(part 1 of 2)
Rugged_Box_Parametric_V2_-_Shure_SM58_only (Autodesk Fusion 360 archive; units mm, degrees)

design "Rugged Box Parametric V2 - Shure SM58 only" references "Shure SM58"
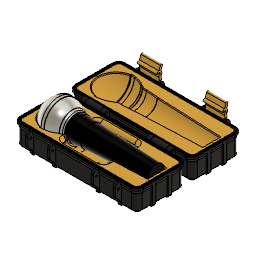
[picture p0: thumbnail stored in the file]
parameter "InnerBoxDepth" = 64 comment "Inner depth"
parameter "InnerBoxWidth" = 170 comment "Inner width"
parameter "InnerBoxBottomHeight" = 30 comment "Inner height of the bottom part"
parameter "ScrewDiameter" = 3 comment "M3 => 3 mm"
parameter "InnerCornerRadius" = 3 comment "Corner radius on the bottom (bottom of champfer)"
parameter "HingeLatchOffset" = 20 comment "Offset of the hinge and latch from inner wall"
parameter "WallThickness" = 2.4 comment "Thickness of the walls"
parameter "RibWidth" = 5 comment "Width of the ribs on the sides"
parameter "InnerChamferSize" = 2 comment "Size of the chamfer on the top and bottom inside the box"
parameter "ScrewThreadDiameter" = 2.85 (= "ScrewDiameter - 0.15 mm") comment "Diameter of the inner holes where you screw in the screw"
parameter "ScrewLength" = 35 comment "Length of the screw to use"
parameter "HingeWidthTolerance" = 0.25 comment "Tolerance of the hinge (width)"
parameter "RibOffset" = 18 comment "Offset of the ribs from inner wall"
parameter "LatchDistance" = 16 comment "Distance between the two screws of the latch"
parameter "InnerBoxLidHeight" = 30 comment "Inner height of the lid"
parameter "HingeLatchHolesTolerance" = 0.4 comment "Tolerance of the hinge and latch holes"
parameter "LatchWidthTolerance" = 0.4 comment "Tollerance of the latch width"
parameter "SealHeight" = 1.4 comment "Height of the seal"
parameter "HingeLatchRibWidth" = 3.2 comment "Width of the ribs for the hinges and latches"
parameter "BoxLatchRibChamferOffset" = 17
parameter "HingeRibChamferOffset" = 5 comment "Offset of the big chamfer on the rib of the hinge side"
parameter "HingeOuterDiameter" = 6.8
parameter "LidLatchRibChamferOffset" = 10 comment "Offset of the big chamfer on the rib of the lid"
parameter "HingeOuterExtend" = 3
sketch "Sketch1" plane through (0, 0, 0) normal (0, 1, 0) x axis (1, 0, 0)
  line L1 (-27, -83) -> (27, -83)
  line L2 (-30, 80) -> (-30, -80)
  line L3 (27, 83) -> (-27, 83)
  line L4 (30, -80) -> (30, 80)
  line L5 (-30, 83) -> (30, -83)
  line L6 (30, 83) -> (-30, -83)
  arc A1 centre (-27, 80) radius 3 clockwise from (-30, 80) to (-27, 83)
  arc A2 centre (27, 80) radius 3 clockwise from (27, 83) to (30, 80)
  arc A3 centre (27, -80) radius 3 clockwise from (30, -80) to (27, -83)
  arc A4 centre (-27, -80) radius 3 clockwise from (-27, -83) to (-30, -80)
  point P6 (0, 0)
  point P1 (0, 0)
  point P4 (-30, 83)
  point P5 (30, 83)
  point P2 (30, -83)
  point P3 (-30, -83)
  horizontal L1
  perpendicular L1 L2
  parallel L1 L3
  parallel L2 L4
  coincident L5 P6
  coincident L6 P6
  coincident P1 P6
  coincident P4 L3
  coincident P4 L2
  tangent L3 A1
  tangent L2 A1
  coincident P5 L3
  coincident P5 L4
  tangent L3 A2
  tangent L4 A2
  coincident P2 L4
  coincident P2 L1
  tangent L4 A3
  tangent L1 A3
  coincident P3 L1
  coincident P3 L2
  tangent L1 A4
  tangent L2 A4
  equal A1 A2
  equal A1 A4
  equal A3 A4
  dimension "d6" distance L1 L3 = 166 (= "InnerBoxWidth - 2 * InnerChamferSize")
  dimension "d7" distance L2 L4 = 60 (= "InnerBoxDepth - 2 * InnerChamferSize")
  dimension "d9" radius A2 = 3 (= "InnerCornerRadius")
sketch "Sketch2" plane through (0, 0, 0) normal (0, 0, 1) x axis (1, 0, 0)
  line L1 (30, 0) -> (0, 0)
  line L2 (30, 2.4) -> (30, 0)
  line L3 (32, 32.4) -> (32, 4.4)
  line L4 (33.23, 32.4) -> (32, 32.4)
  line L5 (33.23, 30.4) -> (33.23, 32.4)
  line L6 (35.03, 30.4) -> (33.23, 30.4)
  line L7 (35.03, 32.4) -> (35.03, 30.4)
  line L8 (36.26, 32.4) -> (35.03, 32.4)
  line L9 (36.26, 29.4) -> (36.26, 32.4)
  line L10 (30, 0) -> (40.1865, 0)
  line L11 (34.4, 29.4) -> (36.26, 29.4)
  line L12 (34.4, 25) -> (34.4, 29.4)
  line L13 (34.4, 3.4059) -> (34.4, 25)
  line L14 (36.26, 29.4) -> (34.4, 25)
  line L15 (30, 2.4) -> (32, 4.4)
  line L16 (34.4, 3.4059) -> (30.9941, 0)
  line L17 (43.26, 3.0735) -> (40.1865, 0)
  line L18 (38.26, 32.4) -> (36.26, 32.4)
  line L19 (43.26, 3.0735) -> (43.26, 27.4)
  line L20 (0, 60) -> (0, 0)
  line L21 (-43.26, 3.0735) -> (-43.26, 27.4)
  line L22 (-33.23, 30.4) -> (-33.23, 32.4)
  line L23 (-36.26, 29.4) -> (-34.4, 25)
  line L24 (-32, 32.4) -> (-32, 4.4)
  line L25 (-30, 2.4) -> (-30, 0)
  line L26 (-35.03, 30.4) -> (-33.23, 30.4)
  line L27 (-34.4, 3.4059) -> (-30.9941, 0)
  line L28 (-34.4, 3.4059) -> (-34.4, 25)
  line L29 (-30, 2.4) -> (-32, 4.4)
  line L30 (-36.26, 29.4) -> (-36.26, 32.4)
  line L31 (-43.26, 3.0735) -> (-40.1865, 0)
  line L32 (-34.4, 25) -> (-34.4, 29.4)
  line L33 (-36.26, 32.4) -> (-35.03, 32.4)
  line L34 (-35.03, 32.4) -> (-35.03, 30.4)
  line L35 (-30, 0) -> (-40.1865, 0)
  line L36 (-34.4, 29.4) -> (-36.26, 29.4)
  line L37 (-33.23, 32.4) -> (-32, 32.4)
  line L38 (32, 29.4) -> (34.4, 29.4)
  line L39 (-32, 29.4) -> (-34.4, 29.4)
  line L40 (-43.26, 27.4) -> (-43.26, 32.4)
  line L41 (-36.46, 32.4) -> (-36.26, 32.4)
  line L42 (-32, 19.7317) -> (-42.2642, 29.9958)
  line L43 (-39.091, 29.9958) -> (-42.2642, 29.9958)
  line L44 (-36.26, 32.4) -> (-39.86, 32.4)
  line L45 (36.26, 2.6355) -> (33.6245, 0)
  line L46 (36.26, 8.4) -> (36.26, 2.6355)
  line L47 (43.26, 15.4) -> (36.26, 8.4)
  line L48 (-36.26, 2.6355) -> (-33.6245, 0)
  line L49 (-36.26, 20.4) -> (-36.26, 2.6355)
  line L50 (-43.26, 27.4) -> (-36.26, 20.4)
  arc A1 centre (38.26, 27.4) radius 5 clockwise from (38.26, 32.4) to (43.26, 27.4)
  circle C1 centre (38.76, 24.4) radius 1.7
  circle C2 centre (-39.86, 32.4) radius 1.7
  circle C3 centre (-39.86, 32.4) radius 3.4
  point P1 (0, 0)
  point P2 (0, 0)
  point P15 (30.9941, 0)
  point P18 (43.26, 32.4)
  point P24 (0, 0)
  point P3 (30, 0)
  point P40 (-30, 0)
  point P4 (30, 2.4)
  point P42 (-30, 2.4)
  point P5 (32, 32.4)
  point P38 (-32, 32.4)
  point P6 (33.23, 32.4)
  point P41 (-33.23, 32.4)
  point P7 (33.23, 30.4)
  point P43 (-33.23, 30.4)
  point P8 (35.03, 30.4)
  point P39 (-35.03, 30.4)
  point P9 (35.03, 32.4)
  point P34 (-35.03, 32.4)
  point P10 (36.26, 32.4)
  point P30 (-36.26, 32.4)
  point P11 (36.26, 29.4)
  point P33 (-36.26, 29.4)
  point P12 (34.4, 29.4)
  point P36 (-34.4, 29.4)
  point P13 (34.4, 25)
  point P29 (-34.4, 25)
  point P14 (32, 4.4)
  point P35 (-32, 4.4)
  point P32 (-30.9941, 0)
  point P16 (34.4, 3.4059)
  point P27 (-34.4, 3.4059)
  point P17 (40.1865, 0)
  point P26 (-40.1865, 0)
  point P37 (-43.26, 32.4)
  point P19 (43.26, 3.0735)
  point P31 (-43.26, 3.0735)
  point P21 (43.26, 27.4)
  point P28 (-43.26, 27.4)
  point P44 (32, 29.4)
  point P45 (-32, 29.4)
  point P48 (-43.26, 32.4)
  point P49 (-36.46, 32.4)
  point P50 (-42.2642, 29.9958)
  point P52 (-32, 19.7317)
  point P46 (-39.86, 32.4)
  point P53 (-39.86, 32.4)
  point P54 (33.6245, 0)
  point P57 (43.26, 15.4)
  point P58 (-33.6245, 0)
  point P55 (36.26, 2.6355)
  point P59 (-36.26, 2.6355)
  point P61 (-43.26, 27.4)
  point P23 (38.76, 24.4)
  coincident P1 P2
  horizontal L1
  perpendicular L1 L2
  perpendicular L3 L4
  perpendicular L4 L5
  perpendicular L5 L6
  perpendicular L6 L7
  perpendicular L7 L8
  perpendicular L8 L9
  perpendicular L2 L10
  perpendicular L9 L11
  perpendicular L11 L12
  perpendicular L10 L13
  coincident L10 P15
  vertical L3
  perpendicular L9 L18
  perpendicular L8 L19
  coincident P18 L18
  coincident P18 L19
  tangent L18 A1
  tangent L19 A1
  coincident P1 P24
  perpendicular L1 L20
  symmetric P3 L20 P40
  symmetric P4 L20 P42
  symmetric P5 L20 P38
  symmetric P6 L20 P41
  symmetric P7 L20 P43
  symmetric P8 L20 P39
  symmetric P9 L20 P34
  symmetric P10 L20 P30
  symmetric P11 L20 P33
  symmetric P12 L20 P36
  symmetric P13 L20 P29
  symmetric P14 L20 P35
  symmetric P15 L20 P32
  symmetric P16 L20 P27
  symmetric P17 L20 P26
  symmetric P18 L20 P37
  symmetric P19 L20 P31
  symmetric P21 L20 P28
  coincident L3 P44
  perpendicular L3 L38
  coincident L24 P45
  perpendicular L24 L39
  concentric C2 C3
  coincident P37 P48
  coincident C3 P49
  horizontal L43
  coincident C3 P50
  tangent C3 L42
  coincident L24 P52
  coincident P46 P53
  perpendicular L30 L44
  horizontal L41
  coincident L10 P54
  perpendicular L10 L46
  coincident L19 P57
  collinear L9 L46
  parallel L16 L45
  symmetric L20 P54 P58
  symmetric L20 P55 P59
  parallel L45 L47
  parallel L28 L49
  coincident L21 P61
  parallel L48 L50
  dimension "d12" distance P2 P3 = 30 (= "InnerBoxDepth / 2 - InnerChamferSize")
  dimension "d13" distance P3 P4 = 2.4 (= "WallThickness")
  dimension "d15" distance P5 P6 = 1.23
  dimension "d16" distance P6 P7 = 2
  dimension "d17" distance P7 P8 = 1.8
  dimension "d18" distance P8 P9 = 2
  dimension "d20" distance P10 P11 = 3
  dimension "d23" distance P12 P13 = 4.4
  dimension "d26" distance L15 L16 = 2.4 (= "WallThickness")
  dimension "d27" distance P4 P14 = 2 (= "InnerChamferSize")
  dimension "d28" distance P4 P14 = 2 (= "InnerChamferSize")
  dimension "d29" distance P3 L8 = 32.4 (= "InnerBoxBottomHeight + WallThickness")
  dimension "d30" distance L16 L17 = 6.5
  dimension "d61" distance P10 P18 = 7
  dimension "d62" radius A1 = 5
  dimension "d63" diameter C1 = 3.4 (= "ScrewDiameter + HingeLatchHolesTolerance")
  dimension "d64" distance L18 P23 = 8 (= "LatchDistance / 2")
  dimension "d65" distance L19 P23 = 4.5
  dimension "d129" distance L7 L9 = 1.23
  dimension "d131" distance L3 L13 = 2.4 (= "WallThickness")
  dimension "d137" diameter C2 = 3.4 (= "ScrewDiameter + HingeLatchHolesTolerance")
  dimension "d138" distance P30 P46 = 3.6 (= "HingeOuterDiameter / 2 + 0.2 mm")
  dimension "d139" diameter C3 = 6.8 (= "HingeOuterDiameter")
  dimension "d140" angle L42 L43 = 45
  dimension "d111" distance L16 L45 = 1.86 (= "d113")
  dimension "d113" distance L9 L12 = 1.86
  dimension "d114" distance L18 P57 = 17 (= "BoxLatchRibChamferOffset")
  dimension "d123" distance L44 P61 = 5 (= "HingeRibChamferOffset")
extrude "Extrude1" new body sketch "Sketch1" profile of L1 L2 L3 L4 A1 A2 A3 A4 along normal blind 2.4 (= "WallThickness")
sweep "Sweep1" sketch "Sketch2" TwistAngle 0 TaperAngle 0
work_plane "WorkPlane2" AlongDistance -14 (= "RibOffset - InnerBoxDepth / 2")
sketch "Sketch4" plane through (-14, 0, 0) normal (1, 0, 0) x axis (0, 0, -1)
  line L1 (-83, 0) -> (0, 0)
  line L2 (-83, 2.4) -> (-83, 0)
  line L3 (-85, 2.4) -> (-83, 2.4)
  line L4 (-85, 4.4) -> (-85, 2.4)
  line L5 (-83, 2.4) -> (-85, 4.4)
  line L6 (-85, 5) -> (-85, 2.4)
  line L7 (-85, 29.4) -> (-85, 2.4)
  line L8 (-89.26, 29.4) -> (-85, 29.4)
  line L9 (-89.26, 2.6355) -> (-89.26, 29.4)
  line L10 (-83, 0) -> (-86.6245, 0)
  line L11 (-89.26, 2.6355) -> (-86.6245, 0)
  line L12 (0, 70) -> (0, 0)
  line L13 (89.26, 2.6355) -> (86.6245, 0)
  line L14 (83, 0) -> (86.6245, 0)
  line L15 (85, 5) -> (85, 2.4)
  line L16 (85, 29.4) -> (85, 2.4)
  line L17 (83, 2.4) -> (85, 4.4)
  line L18 (85, 4.4) -> (85, 2.4)
  line L19 (89.26, 29.4) -> (85, 29.4)
  line L20 (89.26, 2.6355) -> (89.26, 29.4)
  line L21 (83, 2.4) -> (83, 0)
  line L22 (85, 2.4) -> (83, 2.4)
  point P1 (0, 0)
  point P2 (0, 0)
  point P7 (-85, 5)
  point P12 (0, 0)
  point P3 (-83, 0)
  point P16 (83, 0)
  point P4 (-83, 2.4)
  point P18 (83, 2.4)
  point P5 (-85, 2.4)
  point P15 (85, 2.4)
  point P6 (-85, 4.4)
  point P17 (85, 4.4)
  point P22 (85, 5)
  point P8 (-85, 29.4)
  point P14 (85, 29.4)
  point P9 (-89.26, 29.4)
  point P19 (89.26, 29.4)
  point P10 (-89.26, 2.6355)
  point P21 (89.26, 2.6355)
  point P11 (-86.6245, 0)
  point P20 (86.6245, 0)
  coincident P1 P2
  horizontal L1
  perpendicular L1 L2
  perpendicular L2 L3
  perpendicular L3 L4
  coincident L4 P7
  perpendicular L3 L7
  perpendicular L7 L8
  perpendicular L8 L9
  perpendicular L2 L10
  coincident P1 P12
  perpendicular L1 L12
  symmetric P3 L12 P16
  symmetric P4 L12 P18
  symmetric P5 L12 P15
  symmetric P6 L12 P17
  symmetric P7 L12 P22
  symmetric P8 L12 P14
  symmetric P9 L12 P19
  symmetric P10 L12 P21
  symmetric P11 L12 P20
  dimension "d47" distance P2 P3 = 83 (= "InnerBoxWidth / 2 - InnerChamferSize")
  dimension "d48" distance P3 P4 = 2.4 (= "WallThickness")
  dimension "d49" distance P4 P5 = 2 (= "InnerChamferSize")
  dimension "d50" distance P5 P6 = 2 (= "InnerChamferSize")
  dimension "d52" distance P8 P9 = 4.26
  dimension "d53" distance L5 L11 = 4.26 (= "d52")
  dimension "d56" distance L8 L10 = 29.4 (= "InnerBoxBottomHeight - 3 mm + WallThickness")
extrude "Extrude2" add sketch "Sketch4" profile of L2 L3 L4 L5 L6 L7 L8 L9 L10 L11 L13 L14 L15 L16 L17 L18 L19 L20 L21 L22 along a picked direction blind 5 (= "RibWidth")
work_plane "WorkPlane3" AlongDistance 14 (= "InnerBoxDepth / 2 - RibOffset")
sketch "Sketch5" plane through (14, 0, 0) normal (1, 0, 0) x axis (0, 0, -1)
  line L1 (-85, 29.4) -> (-85, 2.4)
  line L2 (-83, 2.4) -> (-85, 4.4)
  line L3 (-85, 2.4) -> (-83, 2.4)
  line L4 (-83, 2.4) -> (-83, 0)
  line L5 (-83, 0) -> (-86.6245, 0)
  line L6 (-89.26, 2.6355) -> (-86.6245, 0)
  line L7 (-89.26, 2.6355) -> (-89.26, 29.4)
  line L8 (-89.26, 29.4) -> (-85, 29.4)
  line L9 (89.26, 29.4) -> (85, 29.4)
  line L10 (89.26, 2.6355) -> (89.26, 29.4)
  line L11 (85, 29.4) -> (85, 2.4)
  line L12 (83, 2.4) -> (85, 4.4)
  line L13 (85, 2.4) -> (83, 2.4)
  line L14 (89.26, 2.6355) -> (86.6245, 0)
  line L15 (83, 2.4) -> (83, 0)
  line L16 (83, 0) -> (86.6245, 0)
extrude "Extrude3" add sketch "Sketch5" along a picked direction no distance stored
work_plane "WorkPlane4" AlongDistance -65 (= "HingeLatchOffset - InnerBoxWidth / 2")
sketch "Sketch6" plane through (0, 0, -65) normal (0, 0, 1) x axis (1, 0, 0)
  line L1 (38.26, 32.4) -> (36.26, 32.4)
  line L2 (43.26, 3.0735) -> (43.26, 27.4)
  line L3 (43.26, 3.0735) -> (40.1865, 0)
  line L4 (30, 0) -> (40.1865, 0)
  line L5 (30, 2.4) -> (30, 0)
  line L6 (30, 2.4) -> (32, 4.4)
  line L7 (32, 32.4) -> (32, 4.4)
  line L8 (32, 29.4) -> (34.4, 29.4)
  line L9 (34.4, 29.4) -> (36.26, 29.4)
  line L10 (36.26, 29.4) -> (36.26, 32.4)
  line L11 (-32, 32.4) -> (-32, 4.4)
  line L12 (-32, 29.4) -> (-34.4, 29.4)
  line L13 (-34.4, 29.4) -> (-36.26, 29.4)
  line L14 (-36.26, 29.4) -> (-36.26, 32.4)
  line L15 (-43.26, 3.0735) -> (-43.26, 27.4)
  line L16 (-43.26, 3.0735) -> (-40.1865, 0)
  line L17 (-30, 0) -> (-40.1865, 0)
  line L18 (-30, 2.4) -> (-30, 0)
  line L19 (-30, 2.4) -> (-32, 4.4)
  line L20 (-43.26, 27.4) -> (-43.26, 32.4)
  line L21 (-36.46, 32.4) -> (-36.26, 32.4)
  line L22 (-32, 19.7317) -> (-42.2642, 29.9958)
  line L23 (43.26, 15.4) -> (36.26, 8.4)
  line L24 (36.26, 8.4) -> (36.26, 2.6355)
  line L25 (36.26, 2.6355) -> (33.6245, 0)
  line L26 (-36.26, 2.6355) -> (-33.6245, 0)
  line L27 (-36.26, 20.4) -> (-36.26, 2.6355)
  line L28 (-43.26, 27.4) -> (-36.26, 20.4)
  arc A1 centre (38.26, 27.4) radius 5 clockwise from (38.26, 32.4) to (43.26, 27.4)
  circle C1 centre (38.76, 24.4) radius 1.7
  circle C2 centre (-39.86, 32.4) radius 3.4
  circle C3 centre (-39.86, 32.4) radius 1.7
extrude "Extrude10" add sketch "Sketch6" profile of L1 L2 A1 L4 L5 L6 L7 L8 L9 L10 L11 L12 L13 L14 L15 L17 L18 L19 C1 L20 C2 C3 L21 L22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 along a picked direction blind 3.2 (= "HingeLatchRibWidth")
extrude "Extrude17" add sketch "Sketch6" profile of L11 L12 L13 L14 C2 C3 L21 L22 along a picked direction blind 6.2 (= "HingeLatchRibWidth + HingeOuterExtend")
work_plane "WorkPlane5" AlongDistance 35 (= "ScrewLength")
sketch "Sketch7" plane through (0, 0, -30) normal (0, 0, 1) x axis (1, 0, 0)
  line L1 (-30, 2.4) -> (-30, 0)
  line L2 (-30, 2.4) -> (-32, 4.4)
  line L3 (-32, 32.4) -> (-32, 4.4)
  line L4 (-32, 29.4) -> (-34.4, 29.4)
  line L5 (-34.4, 29.4) -> (-36.26, 29.4)
  line L6 (-36.26, 29.4) -> (-36.26, 32.4)
  line L7 (-43.26, 3.0735) -> (-43.26, 27.4)
  line L8 (-43.26, 3.0735) -> (-40.1865, 0)
  line L9 (-30, 0) -> (-40.1865, 0)
  line L10 (30, 2.4) -> (30, 0)
  line L11 (30, 2.4) -> (32, 4.4)
  line L12 (32, 32.4) -> (32, 4.4)
  line L13 (32, 29.4) -> (34.4, 29.4)
  line L14 (34.4, 29.4) -> (36.26, 29.4)
  line L15 (36.26, 29.4) -> (36.26, 32.4)
  line L16 (38.26, 32.4) -> (36.26, 32.4)
  line L17 (43.26, 3.0735) -> (43.26, 27.4)
  line L18 (43.26, 3.0735) -> (40.1865, 0)
  line L19 (30, 0) -> (40.1865, 0)
  line L20 (-43.26, 27.4) -> (-43.26, 32.4)
  line L21 (-36.46, 32.4) -> (-36.26, 32.4)
  line L22 (-32, 19.7317) -> (-42.2642, 29.9958)
  line L23 (-36.26, 2.6355) -> (-33.6245, 0)
  line L24 (43.26, 15.4) -> (36.26, 8.4)
  line L25 (36.26, 8.4) -> (36.26, 2.6355)
  line L26 (36.26, 2.6355) -> (33.6245, 0)
  line L27 (-36.26, 20.4) -> (-36.26, 2.6355)
  line L28 (-43.26, 27.4) -> (-36.26, 20.4)
  arc A1 centre (38.26, 27.4) radius 5 clockwise from (38.26, 32.4) to (43.26, 27.4)
  circle C1 centre (38.76, 24.4) radius 1.7
  circle C2 centre (-39.86, 32.4) radius 3.4
  circle C3 centre (-39.86, 32.4) radius 1.7
  circle C4 centre (38.76, 24.4) radius 1.425
  circle C5 centre (-39.86, 32.4) radius 1.425
  concentric C1 C4
  concentric C2 C5
  dimension "d24" diameter C4 = 2.85 (= "ScrewThreadDiameter")
  dimension "d25" diameter C5 = 2.85 (= "ScrewThreadDiameter")
extrude "Extrude11" add sketch "Sketch7" profile of L1 L2 L3 L4 L5 L6 L7 L9 L10 L11 L12 L13 L14 L15 L16 A1 L17 L19 L20 C2 L21 L22 C4 C5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 along a picked direction no distance stored
extrude "Extrude18" add sketch "Sketch7" profile of L3 L4 L5 L6 C2 L21 L22 C5 along a picked direction no distance stored
work_plane "WorkPlane6" AlongDistance 65 (= "-( HingeLatchOffset - InnerBoxWidth / 2 )")
sketch "Sketch8" plane through (0, 0, 65) normal (0, 0, 1) x axis (1, 0, 0)
  line L1 (-43.26, 3.0735) -> (-43.26, 27.4)
  line L2 (-36.26, 29.4) -> (-36.26, 32.4)
  line L3 (-34.4, 29.4) -> (-36.26, 29.4)
  line L4 (-32, 29.4) -> (-34.4, 29.4)
  line L5 (-32, 32.4) -> (-32, 4.4)
  line L6 (-30, 2.4) -> (-32, 4.4)
  line L7 (-30, 2.4) -> (-30, 0)
  line L8 (-30, 0) -> (-40.1865, 0)
  line L9 (-43.26, 3.0735) -> (-40.1865, 0)
  line L10 (30, 2.4) -> (30, 0)
  line L11 (30, 2.4) -> (32, 4.4)
  line L12 (32, 32.4) -> (32, 4.4)
  line L13 (32, 29.4) -> (34.4, 29.4)
  line L14 (34.4, 29.4) -> (36.26, 29.4)
  line L15 (36.26, 29.4) -> (36.26, 32.4)
  line L16 (38.26, 32.4) -> (36.26, 32.4)
  line L17 (43.26, 3.0735) -> (43.26, 27.4)
  line L18 (43.26, 3.0735) -> (40.1865, 0)
  line L19 (30, 0) -> (40.1865, 0)
  line L20 (-43.26, 27.4) -> (-43.26, 32.4)
  line L21 (-36.46, 32.4) -> (-36.26, 32.4)
  line L22 (-32, 19.7317) -> (-42.2642, 29.9958)
  line L23 (43.26, 15.4) -> (36.26, 8.4)
  line L24 (36.26, 8.4) -> (36.26, 2.6355)
  line L25 (36.26, 2.6355) -> (33.6245, 0)
  line L26 (-36.26, 2.6355) -> (-33.6245, 0)
  line L27 (-36.26, 20.4) -> (-36.26, 2.6355)
  line L28 (-43.26, 27.4) -> (-36.26, 20.4)
  arc A1 centre (38.26, 27.4) radius 5 clockwise from (38.26, 32.4) to (43.26, 27.4)
  circle C1 centre (38.76, 24.4) radius 1.7
  circle C2 centre (-39.86, 32.4) radius 3.4
  circle C3 centre (-39.86, 32.4) radius 1.7
extrude "Extrude12" add sketch "Sketch8" profile of L1 L2 L3 L4 L5 L6 L7 L8 L10 L11 L12 L13 L14 L15 L16 A1 L17 C1 L19 L20 C2 C3 L21 L22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 along a picked direction no distance stored
extrude "Extrude19" add sketch "Sketch8" profile of L2 L3 L4 L5 C2 C3 L21 L22 along a picked direction no distance stored
work_plane "WorkPlane7"
sketch "Sketch9" plane through (0, 0, 30) normal (0, 0, 1) x axis (1, 0, 0)
  line L1 (43.26, 3.0735) -> (40.1865, 0)
  line L2 (30, 0) -> (40.1865, 0)
  line L3 (43.26, 3.0735) -> (43.26, 27.4)
  line L4 (38.26, 32.4) -> (36.26, 32.4)
  line L5 (36.26, 29.4) -> (36.26, 32.4)
  line L6 (34.4, 29.4) -> (36.26, 29.4)
  line L7 (32, 29.4) -> (34.4, 29.4)
  line L8 (32, 32.4) -> (32, 4.4)
  line L9 (30, 2.4) -> (32, 4.4)
  line L10 (30, 2.4) -> (30, 0)
  line L11 (-30, 2.4) -> (-30, 0)
  line L12 (-30, 2.4) -> (-32, 4.4)
  line L13 (-32, 32.4) -> (-32, 4.4)
  line L14 (-32, 29.4) -> (-34.4, 29.4)
  line L15 (-34.4, 29.4) -> (-36.26, 29.4)
  line L16 (-36.26, 29.4) -> (-36.26, 32.4)
  line L17 (-43.26, 3.0735) -> (-43.26, 27.4)
  line L18 (-43.26, 3.0735) -> (-40.1865, 0)
  line L19 (-30, 0) -> (-40.1865, 0)
  line L20 (-43.26, 27.4) -> (-43.26, 32.4)
  line L21 (-36.46, 32.4) -> (-36.26, 32.4)
  line L22 (-32, 19.7317) -> (-42.2642, 29.9958)
  line L23 (43.26, 15.4) -> (36.26, 8.4)
  line L24 (36.26, 8.4) -> (36.26, 2.6355)
  line L25 (36.26, 2.6355) -> (33.6245, 0)
  line L26 (-36.26, 2.6355) -> (-33.6245, 0)
  line L27 (-36.26, 20.4) -> (-36.26, 2.6355)
  line L28 (-43.26, 27.4) -> (-36.26, 20.4)
  arc A1 centre (38.26, 27.4) radius 5 clockwise from (38.26, 32.4) to (43.26, 27.4)
  circle C1 centre (38.76, 24.4) radius 1.7
  circle C2 centre (-39.86, 32.4) radius 3.4
  circle C3 centre (-39.86, 32.4) radius 1.7
  circle C4 centre (38.76, 24.4) radius 1.425
  circle C5 centre (-39.86, 32.4) radius 1.425
  concentric C1 C4
  concentric C2 C5
  dimension "d39" diameter C4 = 2.85 (= "ScrewThreadDiameter")
  dimension "d40" diameter C5 = 2.85 (= "ScrewThreadDiameter")
extrude "Extrude13" add sketch "Sketch9" profile of L2 L3 A1 L4 L5 L6 L7 L8 L9 L10 L11 L12 L13 L14 L15 L16 L17 L19 L20 C2 L21 L22 C4 C5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 along a picked direction blind 3.2 (= "HingeLatchRibWidth")
extrude "Extrude20" add sketch "Sketch9" profile of L13 L14 L15 L16 C2 L21 L22 C5 along a picked direction blind 6.2 (= "HingeLatchRibWidth + HingeOuterExtend")
fillet "Fillet2" radius 1
fillet "Fillet3" radius 3
component_from_bodies "Body->Comp1"
sketch "Sketch10" plane through (0, 0, 0) normal (0, 0, 1) x axis (1, 0, 0)
  line L1 (156.2863, 42.7568) -> (153.4854, 42.7568)
  line L2 (149.3136, 34.5236) -> (152.4867, 44.0068)
  line L3 (147.7963, 35.0313) -> (150.9693, 44.5145)
  line L4 (150.8309, 34.0159) -> (154.004, 43.4992)
  line L5 (152.8792, 47.9875) -> (152.4973, 45.6068)
  line L6 (152.4867, 44.0068) -> (152.4867, 60.0068)
  circle C1 centre (152.4867, 44.0068) radius 1.6
  circle C2 centre (152.4867, 44.0068) radius 4
  circle C3 centre (152.4867, 60.0068) radius 1.6
  circle C4 centre (152.4867, 60.0068) radius 4
  arc A1 centre (171.1154, 52.0068) radius 20.2738 clockwise from (152.4867, 44.0068) to (152.4867, 60.0068)
  arc A2 centre (171.1154, 52.0068) radius 21.8738 clockwise from (151.0165, 43.3755) to (151.0165, 60.6382)
  arc A3 centre (171.1154, 52.0068) radius 18.6738 clockwise from (153.9568, 44.6382) to (153.9568, 59.3755)
  circle C5 centre (149.3136, 34.5236) radius 1.6
  point P3 (152.4867, 44.0068)
  point P4 (152.4867, 44.0068)
  point P5 (152.4867, 60.0068)
  point P6 (152.4867, 60.0068)
  point P15 (153.4854, 42.7568)
  point P16 (156.2863, 42.7568)
  point P2 (152.4867, 44.0068)
  point P17 (152.4867, 44.0068)
  point P18 (149.3136, 34.5236)
  point P19 (149.3136, 34.5236)
  point P24 (152.4973, 45.6068)
  point P25 (152.8792, 47.9875)
  point P26 (152.4867, 60.0068)
  point P27 (152.4867, 44.0068)
  point P14 (153.9568, 59.3755)
  point P11 (151.0165, 60.6382)
  point P10 (151.0165, 43.3755)
  point P13 (153.9568, 44.6382)
  point P22 (154.004, 43.4992)
  point P20 (150.9693, 44.5145)
  point P21 (147.7963, 35.0313)
  point P23 (150.8309, 34.0159)
  concentric C1 C2
  coincident P3 P4
  coincident P5 P6
  concentric C3 C4
  coincident C1 P15
  coincident C2 P16
  coincident P2 P17
  coincident P18 P19
  coincident C1 P24
  coincident A3 P25
  coincident C2 P25
  concentric A1 A3
  concentric A1 A2
  coincident P6 P26
  coincident P2 P27
  vertical L6
  coincident C3 P14
  tangent C3 A3
  tangent C3 A2
  coincident C3 P11
  coincident C1 P10
  coincident C1 P13
  parallel L2 L3
  parallel L2 L4
  coincident C1 P22
  coincident C1 P20
  tangent C1 L3
  tangent C1 L4
  coincident C5 P21
  coincident C5 P23
  horizontal L1
  dimension "d98" diameter C1 = 3.2 (= "ScrewDiameter + 0.2 mm")
  dimension "d99" diameter C2 = 8
  dimension "d100" distance P4 P5 = 16 (= "LatchDistance")
  dimension "d101" diameter C3 = 3.2 (= "ScrewDiameter + 0.2 mm")
  dimension "d102" diameter C4 = 8
  dimension "d105" diameter C5 = 3.2 (= "ScrewDiameter + 0.2 mm")
  dimension "d66" distance P17 P18 = 10
  dimension "d67" angle L2 L6 = 161.5
  dimension "d69" distance P2 L1 = 1.25
extrude "Extrude15" new body sketch "Sketch10" profile of C1 C2 C3 C4 A1 A2 A3 L1 L2 C5 L3 L4 L5 along a picked direction blind 28.2 (= "( ScrewLength - 2 * HingeLatchRibWidth ) - LatchWidthTolerance")
component_from_bodies "Body->Comp3"
sketch "Sketch1" plane through (0, 0, 0) normal (0, 1, 0) x axis (1, 0, 0)
  line L1 (-27, -83) -> (27, -83)
  line L2 (-30, 80) -> (-30, -80)
  line L3 (27, 83) -> (-27, 83)
  line L4 (30, -80) -> (30, 80)
  line L5 (-30, 83) -> (30, -83)
  line L6 (30, 83) -> (-30, -83)
  arc A1 centre (-27, 80) radius 3 clockwise from (-30, 80) to (-27, 83)
  arc A2 centre (27, 80) radius 3 clockwise from (27, 83) to (30, 80)
  arc A3 centre (27, -80) radius 3 clockwise from (30, -80) to (27, -83)
  arc A4 centre (-27, -80) radius 3 clockwise from (-27, -83) to (-30, -80)
  point P6 (0, 0)
  point P1 (0, 0)
  point P4 (-30, 83)
  point P5 (30, 83)
  point P2 (30, -83)
  point P3 (-30, -83)
  horizontal L1
  perpendicular L1 L2
  parallel L1 L3
  parallel L2 L4
  coincident L5 P6
  coincident L6 P6
  coincident P1 P6
  coincident P4 L3
  coincident P4 L2
  tangent L3 A1
  tangent L2 A1
  coincident P5 L3
  coincident P5 L4
  tangent L3 A2
  tangent L4 A2
  coincident P2 L4
  coincident P2 L1
  tangent L4 A3
  tangent L1 A3
  coincident P3 L1
  coincident P3 L2
  tangent L1 A4
  tangent L2 A4
  equal A1 A2
  equal A1 A4
  equal A3 A4
  dimension "d6_1" distance L1 L3 = 166 (= "InnerBoxWidth - 2 * InnerChamferSize")
  dimension "d7_1" distance L2 L4 = 60 (= "InnerBoxDepth - 2 * InnerChamferSize")
  dimension "d9_1" radius A2 = 3 (= "InnerCornerRadius")
sketch "Sketch2" plane through (0, 0, 0) normal (0, 0, 1) x axis (1, 0, 0)
  line L1 (30, 0) -> (0, 0)
  line L2 (30, 2.4) -> (30, 0)
  line L3 (32, 32.4) -> (32, 4.4)
  line L4 (33.23, 32.4) -> (32, 32.4)
  line L5 (33.23, 30.4) -> (33.23, 32.4)
  line L6 (35.03, 30.4) -> (33.23, 30.4)
  line L7 (35.03, 32.4) -> (35.03, 30.4)
  line L8 (36.26, 32.4) -> (35.03, 32.4)
  line L9 (36.26, 29.4) -> (36.26, 32.4)
  line L10 (30, 0) -> (40.1865, 0)
  line L11 (34.4, 29.4) -> (36.26, 29.4)
  line L12 (34.4, 25) -> (34.4, 29.4)
  line L13 (34.4, 3.4059) -> (34.4, 25)
  line L14 (36.26, 29.4) -> (34.4, 25)
  line L15 (30, 2.4) -> (32, 4.4)
  line L16 (34.4, 3.4059) -> (30.9941, 0)
  line L17 (43.26, 3.0735) -> (40.1865, 0)
  line L18 (38.26, 32.4) -> (36.26, 32.4)
  line L19 (43.26, 3.0735) -> (43.26, 27.4)
  line L20 (0, 60) -> (0, 0)
  line L21 (-33.23, 30.4) -> (-33.23, 32.4)
  line L22 (-36.26, 29.4) -> (-34.4, 25)
  line L23 (-32, 32.4) -> (-32, 4.4)
  line L24 (-30, 2.4) -> (-30, 0)
  line L25 (-35.03, 30.4) -> (-33.23, 30.4)
  line L26 (-34.4, 3.4059) -> (-30.9941, 0)
  line L27 (-34.4, 3.4059) -> (-34.4, 25)
  line L28 (-30, 2.4) -> (-32, 4.4)
  line L29 (-36.26, 29.4) -> (-36.26, 32.4)
  line L30 (-34.4, 25) -> (-34.4, 29.4)
  line L31 (-36.26, 32.4) -> (-35.03, 32.4)
  line L32 (-35.03, 32.4) -> (-35.03, 30.4)
  line L33 (-34.4, 29.4) -> (-36.26, 29.4)
  line L34 (-33.23, 32.4) -> (-32, 32.4)
  line L35 (32, 29.4) -> (34.4, 29.4)
  line L36 (-32, 29.4) -> (-34.4, 29.4)
  line L37 (35.03, 32.4) -> (33.23, 32.4)
  line L38 (34.13, 33.3) -> (34.13, 32.4)
  line L39 (34.33, 33.3) -> (34.13, 33.3)
  line L40 (34.33, 33.06) -> (34.33, 33.3)
  line L41 (33.93, 33.3) -> (34.13, 33.3)
  line L42 (33.93, 33.06) -> (33.93, 33.3)
  line L43 (33.38, 30.4) -> (33.38, 32.4)
  line L44 (34.88, 32.4) -> (34.88, 30.4)
  line L45 (34.13, 33.3) -> (33.38, 32.4)
  line L46 (34.88, 32.4) -> (34.13, 33.3)
  line L47 (-36.46, 32.4) -> (-36.26, 32.4)
  line L48 (-34.4, 22.1317) -> (-42.2642, 29.9958)
  line L49 (-89.0433, 29.9958) -> (-42.2642, 29.9958)
  line L50 (-30.9941, 0) -> (-30, 0)
  line L51 (-30, 0) -> (-40.1865, 0)
  line L52 (-43.26, 3.0735) -> (-40.1865, 0)
  line L53 (-43.26, 3.0735) -> (-43.26, 27.4)
  line L54 (-43.26, 32.4) -> (-43.26, 27.4)
  line L55 (-36.26, 32.4) -> (-39.86, 32.4)
  line L56 (36.26, 2.6355) -> (33.6245, 0)
  line L57 (36.26, 15.4) -> (36.26, 2.6355)
  line L58 (43.26, 22.4) -> (36.26, 15.4)
  line L59 (-36.26, 2.6355) -> (-33.6245, 0)
  line L60 (-36.26, 20.4) -> (-36.26, 2.6355)
  line L61 (-43.26, 27.4) -> (-36.26, 20.4)
  arc A1 centre (38.26, 27.4) radius 5 clockwise from (38.26, 32.4) to (43.26, 27.4)
  circle C1 centre (38.76, 24.4) radius 1.7
  circle C2 centre (-39.86, 32.4) radius 1.7
  circle C3 centre (-39.86, 32.4) radius 3.4
  point P1 (0, 0)
  point P2 (0, 0)
  point P15 (30.9941, 0)
  point P18 (43.26, 32.4)
  point P24 (0, 0)
  point P3 (30, 0)
  point P37 (-30, 0)
  point P4 (30, 2.4)
  point P39 (-30, 2.4)
  point P5 (32, 32.4)
  point P35 (-32, 32.4)
  point P6 (33.23, 32.4)
  point P38 (-33.23, 32.4)
  point P7 (33.23, 30.4)
  point P40 (-33.23, 30.4)
  point P8 (35.03, 30.4)
  point P36 (-35.03, 30.4)
  point P9 (35.03, 32.4)
  point P31 (-35.03, 32.4)
  point P10 (36.26, 32.4)
  point P28 (-36.26, 32.4)
  point P11 (36.26, 29.4)
  point P30 (-36.26, 29.4)
  point P12 (34.4, 29.4)
  point P33 (-34.4, 29.4)
  point P13 (34.4, 25)
  point P27 (-34.4, 25)
  point P14 (32, 4.4)
  point P32 (-32, 4.4)
  point P29 (-30.9941, 0)
  point P16 (34.4, 3.4059)
  point P26 (-34.4, 3.4059)
  point P34 (-43.26, 32.4)
  point P41 (32, 29.4)
  point P42 (-32, 29.4)
  point P43 (34.13, 32.4)
  point P47 (33.38, 32.4)
  point P48 (33.38, 30.4)
  point P49 (34.88, 30.4)
  point P50 (34.88, 32.4)
  point P51 (33.93, 33.06)
  point P52 (34.33, 33.06)
  point P55 (-36.46, 32.4)
  point P56 (-42.2642, 29.9958)
  point P57 (-34.4, 22.1317)
  point P60 (-30, 0)
  point P17 (40.1865, 0)
  point P59 (-40.1865, 0)
  point P19 (43.26, 3.0735)
  point P61 (-43.26, 3.0735)
  point P21 (43.26, 27.4)
  point P62 (-43.26, 27.4)
  point P63 (-43.26, 32.4)
  point P54 (-39.86, 32.4)
  point P64 (-39.86, 32.4)
  point P65 (33.6245, 0)
  point P68 (43.26, 22.4)
  point P70 (-33.6245, 0)
  point P66 (36.26, 2.6355)
  point P69 (-36.26, 2.6355)
  point P72 (-43.26, 27.4)
  point P23 (38.76, 24.4)
  point P46 (33.93, 33.3)
  point P45 (34.33, 33.3)
  point P53 (-39.86, 32.4)
  coincident P1 P2
  horizontal L1
  perpendicular L1 L2
  perpendicular L3 L4
  perpendicular L4 L5
  perpendicular L5 L6
  perpendicular L6 L7
  perpendicular L7 L8
  perpendicular L8 L9
  perpendicular L2 L10
  perpendicular L9 L11
  perpendicular L11 L12
  perpendicular L10 L13
  coincident L10 P15
  vertical L3
  perpendicular L9 L18
  perpendicular L8 L19
  coincident P18 L18
  coincident P18 L19
  tangent L18 A1
  tangent L19 A1
  coincident P1 P24
  perpendicular L1 L20
  symmetric P3 L20 P37
  symmetric P4 L20 P39
  symmetric P5 L20 P35
  symmetric P6 L20 P38
  symmetric P7 L20 P40
  symmetric P8 L20 P36
  symmetric P9 L20 P31
  symmetric P10 L20 P28
  symmetric P11 L20 P30
  symmetric P12 L20 P33
  symmetric P13 L20 P27
  symmetric P14 L20 P32
  symmetric P15 L20 P29
  symmetric P16 L20 P26
  symmetric P18 L20 P34
  coincident L3 P41
  perpendicular L3 L35
  coincident L23 P42
  perpendicular L23 L36
  midpoint L37 P43
  perpendicular L37 L38
  perpendicular L38 L39
  perpendicular L37 L40
  perpendicular L40 L41
  perpendicular L41 L42
  coincident L37 P47
  coincident L6 P48
  perpendicular L6 L43
  coincident L6 P49
  coincident L37 P50
  perpendicular L37 L44
  coincident L45 P51
  coincident L46 P52
  concentric C2 C3
  coincident C3 P55
  horizontal L49
  coincident C3 P56
  coincident L27 P57
  tangent C3 L48
  symmetric P3 L20 P60
  symmetric P17 L20 P59
  symmetric P19 L20 P61
  symmetric P21 L20 P62
  coincident P34 P63
  horizontal L47
  coincident P54 P64
  perpendicular L29 L55
  coincident L10 P65
  perpendicular L10 L57
  coincident L19 P68
  parallel L56 L58
  parallel L16 L56
  collinear L9 L57
  symmetric L20 P65 P70
  symmetric L20 P66 P69
  vertical L60
  coincident L53 P72
  parallel L59 L61
  dimension "d12_1" distance P2 P3 = 30 (= "InnerBoxDepth / 2 - InnerChamferSize")
  dimension "d13_1" distance P3 P4 = 2.4 (= "WallThickness")
  dimension "d15_1" distance P5 P6 = 1.23
  dimension "d16_1" distance P6 P7 = 2
  dimension "d17_1" distance P7 P8 = 1.8
  dimension "d18_1" distance P8 P9 = 2
  dimension "d19" distance P9 P10 = 1.23
  dimension "d20_1" distance P10 P11 = 3
  dimension "d23_1" distance P12 P13 = 4.4
  dimension "d26_1" distance L15 L16 = 2.4 (= "WallThickness")
  dimension "d27_1" distance P4 P14 = 2 (= "InnerChamferSize")
  dimension "d28_1" distance P4 P14 = 2 (= "InnerChamferSize")
  dimension "d29_1" distance P3 L8 = 32.4 (= "InnerBoxLidHeight + WallThickness")
  dimension "d30_1" distance L16 L17 = 6.5
  dimension "d61_1" distance P10 P18 = 7
  dimension "d62_1" radius A1 = 5
  dimension "d63_1" diameter C1 = 3.4 (= "ScrewDiameter + HingeLatchHolesTolerance")
  dimension "d64_1" distance L18 P23 = 8 (= "LatchDistance / 2")
  dimension "d65_1" distance L19 P23 = 4.5
  dimension "d134" distance L3 L13 = 2.4 (= "WallThickness")
  dimension "d135" distance L5 L43 = 0.15
  dimension "d136" distance L7 L44 = 0.15
  dimension "d137_1" angle L45 L46 = 79.611
  dimension "d138_1" distance P46 P51 = 0.24
  dimension "d139_1" distance P45 P52 = 0.24
  dimension "d156" diameter C2 = 3.4 (= "ScrewDiameter + HingeLatchHolesTolerance")
  dimension "d157" distance P28 P53 = 3.6 (= "HingeOuterDiameter / 2 + 0.2 mm")
  dimension "d158" diameter C3 = 6.8 (= "HingeOuterDiameter")
  dimension "d159" angle L48 L49 = 45
  dimension "d116" distance L9 L12 = 1.86
  dimension "d117" distance L16 L56 = 1.86 (= "d116")
  dimension "d118" distance L18 P68 = 10 (= "LidLatchRibChamferOffset")
  dimension "d125" distance L55 P72 = 5 (= "HingeRibChamferOffset")
extrude "Extrude1" new body sketch "Sketch1" profile of L1 L2 L3 L4 A1 A2 A3 A4 along a picked direction blind 2.4 (= "WallThickness") named "d31_1" bodies "Box Waterproof"
sweep "Sweep1" sketch "Sketch2" TwistAngle 0 named "d37_1" TaperAngle 0 named "d38_1"
work_plane "WorkPlane2" AlongDistance -14 (= "RibOffset - InnerBoxDepth / 2") named "d46_1"
sketch "Sketch4" plane through (-14, 0, 0) normal (1, 0, 0) x axis (0, 0, -1)
  line L1 (-83, 0) -> (0, 0)
  line L2 (-83, 2.4) -> (-83, 0)
  line L3 (-85, 2.4) -> (-83, 2.4)
  line L4 (-85, 4.4) -> (-85, 2.4)
  line L5 (-83, 2.4) -> (-85, 4.4)
  line L6 (-85, 5) -> (-85, 2.4)
  line L7 (-85, 29.4) -> (-85, 2.4)
  line L8 (-89.26, 29.4) -> (-85, 29.4)
  line L9 (-89.26, 2.6355) -> (-89.26, 29.4)
  line L10 (-83, 0) -> (-86.6245, 0)
  line L11 (-89.26, 2.6355) -> (-86.6245, 0)
  line L12 (0, 70) -> (0, 0)
  line L13 (89.26, 2.6355) -> (86.6245, 0)
  line L14 (83, 0) -> (86.6245, 0)
  line L15 (85, 5) -> (85, 2.4)
  line L16 (85, 29.4) -> (85, 2.4)
  line L17 (83, 2.4) -> (85, 4.4)
  line L18 (85, 4.4) -> (85, 2.4)
  line L19 (89.26, 29.4) -> (85, 29.4)
  line L20 (89.26, 2.6355) -> (89.26, 29.4)
  line L21 (83, 2.4) -> (83, 0)
  line L22 (85, 2.4) -> (83, 2.4)
  point P1 (0, 0)
  point P2 (0, 0)
  point P7 (-85, 5)
  point P12 (0, 0)
  point P3 (-83, 0)
  point P16 (83, 0)
  point P4 (-83, 2.4)
  point P18 (83, 2.4)
  point P5 (-85, 2.4)
  point P15 (85, 2.4)
  point P6 (-85, 4.4)
  point P17 (85, 4.4)
  point P22 (85, 5)
  point P8 (-85, 29.4)
  point P14 (85, 29.4)
  point P9 (-89.26, 29.4)
  point P19 (89.26, 29.4)
  point P10 (-89.26, 2.6355)
  point P21 (89.26, 2.6355)
  point P11 (-86.6245, 0)
  point P20 (86.6245, 0)
  coincident P1 P2
  horizontal L1
  perpendicular L1 L2
  perpendicular L2 L3
  perpendicular L3 L4
  coincident L4 P7
  perpendicular L3 L7
  perpendicular L7 L8
  perpendicular L8 L9
  perpendicular L2 L10
  coincident P1 P12
  perpendicular L1 L12
  symmetric P3 L12 P16
  symmetric P4 L12 P18
  symmetric P5 L12 P15
  symmetric P6 L12 P17
  symmetric P7 L12 P22
  symmetric P8 L12 P14
  symmetric P9 L12 P19
  symmetric P10 L12 P21
  symmetric P11 L12 P20
  dimension "d47_1" distance P2 P3 = 83 (= "InnerBoxWidth / 2 - InnerChamferSize")
  dimension "d48_1" distance P3 P4 = 2.4 (= "WallThickness")
  dimension "d49_1" distance P4 P5 = 2 (= "InnerChamferSize")
  dimension "d50_1" distance P5 P6 = 2 (= "InnerChamferSize")
  dimension "d52_1" distance P8 P9 = 4.26
  dimension "d53_1" distance L5 L11 = 4.26 (= "d52_1")
  dimension "d56_1" distance L8 L10 = 29.4 (= "InnerBoxLidHeight - 3 mm + WallThickness")
extrude "Extrude2" add sketch "Sketch4" profile of L2 L3 L4 L5 L6 L7 L8 L9 L10 L11 L13 L14 L15 L16 L17 L18 L19 L20 L21 L22 along a picked direction blind 5 (= "RibWidth") named "d54_1" bodies "Box Waterproof"
work_plane "WorkPlane3" AlongDistance 14 (= "InnerBoxDepth / 2 - RibOffset") named "d57_1"
sketch "Sketch5" plane through (14, 0, 0) normal (1, 0, 0) x axis (0, 0, -1)
  line L1 (-85, 29.4) -> (-85, 2.4)
  line L2 (-83, 2.4) -> (-85, 4.4)
  line L3 (-85, 2.4) -> (-83, 2.4)
  line L4 (-83, 2.4) -> (-83, 0)
  line L5 (-83, 0) -> (-86.6245, 0)
  line L6 (-89.26, 2.6355) -> (-86.6245, 0)
  line L7 (-89.26, 2.6355) -> (-89.26, 29.4)
  line L8 (-89.26, 29.4) -> (-85, 29.4)
  line L9 (89.26, 29.4) -> (85, 29.4)
  line L10 (89.26, 2.6355) -> (89.26, 29.4)
  line L11 (85, 29.4) -> (85, 2.4)
  line L12 (83, 2.4) -> (85, 4.4)
  line L13 (85, 2.4) -> (83, 2.4)
  line L14 (89.26, 2.6355) -> (86.6245, 0)
  line L15 (83, 2.4) -> (83, 0)
  line L16 (83, 0) -> (86.6245, 0)
extrude "Extrude3" add sketch "Sketch5" along a picked direction no distance stored
work_plane "WorkPlane4" AlongDistance -65 (= "HingeLatchOffset - InnerBoxWidth / 2") named "d60_1"
sketch "Sketch6" plane through (0, 0, -65) normal (0, 0, 1) x axis (1, 0, 0)
  line L1 (38.26, 32.4) -> (36.26, 32.4)
  line L2 (43.26, 3.0735) -> (43.26, 27.4)
  line L3 (43.26, 3.0735) -> (40.1865, 0)
  line L4 (30, 0) -> (40.1865, 0)
  line L5 (30, 2.4) -> (30, 0)
  line L6 (30, 2.4) -> (32, 4.4)
  line L7 (32, 32.4) -> (32, 4.4)
  line L8 (32, 29.4) -> (34.4, 29.4)
  line L9 (34.4, 29.4) -> (36.26, 29.4)
  line L10 (36.26, 29.4) -> (36.26, 32.4)
  line L11 (43.26, 22.4) -> (36.26, 15.4)
  line L12 (36.26, 15.4) -> (36.26, 2.6355)
  line L13 (36.26, 2.6355) -> (33.6245, 0)
  arc A1 centre (38.26, 27.4) radius 5 clockwise from (38.26, 32.4) to (43.26, 27.4)
  circle C1 centre (38.76, 24.4) radius 1.7
extrude "Extrude10" add sketch "Sketch6" profile of L1 L2 A1 L4 L5 L6 L7 L8 L9 L10 C1 L11 L12 L13 along a picked direction blind 3.2 (= "HingeLatchRibWidth") named "d81_1"
work_plane "WorkPlane5" AlongDistance 35 (= "ScrewLength") named "d68_1"
sketch "Sketch7" plane through (0, 0, -30) normal (0, 0, 1) x axis (1, 0, 0)
  line L1 (30, 2.4) -> (30, 0)
  line L2 (30, 2.4) -> (32, 4.4)
  line L3 (32, 32.4) -> (32, 4.4)
  line L4 (32, 29.4) -> (34.4, 29.4)
  line L5 (34.4, 29.4) -> (36.26, 29.4)
  line L6 (36.26, 29.4) -> (36.26, 32.4)
  line L7 (38.26, 32.4) -> (36.26, 32.4)
  line L8 (43.26, 3.0735) -> (43.26, 27.4)
  line L9 (43.26, 3.0735) -> (40.1865, 0)
  line L10 (30, 0) -> (40.1865, 0)
  line L11 (43.26, 22.4) -> (36.26, 15.4)
  line L12 (36.26, 15.4) -> (36.26, 2.6355)
  line L13 (36.26, 2.6355) -> (33.6245, 0)
  arc A1 centre (38.26, 27.4) radius 5 clockwise from (38.26, 32.4) to (43.26, 27.4)
  circle C1 centre (38.76, 24.4) radius 1.7
  circle C2 centre (38.76, 24.4) radius 1.425
  concentric C1 C2
  dimension "d41" diameter C2 = 2.85 (= "ScrewThreadDiameter")
extrude "Extrude11" add sketch "Sketch7" profile of L1 L2 L3 L4 L5 L6 L7 A1 L8 L10 C2 L11 L12 L13 along a picked direction no distance stored
work_plane "WorkPlane6" AlongDistance 65 (= "-( HingeLatchOffset - InnerBoxWidth / 2 )") named "d71_1"
sketch "Sketch8" plane through (0, 0, 65) normal (0, 0, 1) x axis (1, 0, 0)
  line L1 (30, 2.4) -> (30, 0)
  line L2 (30, 2.4) -> (32, 4.4)
  line L3 (32, 32.4) -> (32, 4.4)
  line L4 (32, 29.4) -> (34.4, 29.4)
  line L5 (34.4, 29.4) -> (36.26, 29.4)
  line L6 (36.26, 29.4) -> (36.26, 32.4)
  line L7 (38.26, 32.4) -> (36.26, 32.4)
  line L8 (43.26, 3.0735) -> (43.26, 27.4)
  line L9 (43.26, 3.0735) -> (40.1865, 0)
  line L10 (30, 0) -> (40.1865, 0)
  line L11 (43.26, 22.4) -> (36.26, 15.4)
  line L12 (36.26, 15.4) -> (36.26, 2.6355)
  line L13 (36.26, 2.6355) -> (33.6245, 0)
  arc A1 centre (38.26, 27.4) radius 5 clockwise from (38.26, 32.4) to (43.26, 27.4)
  circle C1 centre (38.76, 24.4) radius 1.7
extrude "Extrude12" add sketch "Sketch8" profile of L1 L2 L3 L4 L5 L6 L7 A1 L8 C1 L10 L11 L12 L13 along a picked direction no distance stored
work_plane "WorkPlane7"
sketch "Sketch9" plane through (0, 0, 30) normal (0, 0, 1) x axis (1, 0, 0)
  line L1 (43.26, 3.0735) -> (40.1865, 0)
  line L2 (30, 0) -> (40.1865, 0)
  line L3 (43.26, 3.0735) -> (43.26, 27.4)
  line L4 (38.26, 32.4) -> (36.26, 32.4)
  line L5 (36.26, 29.4) -> (36.26, 32.4)
  line L6 (34.4, 29.4) -> (36.26, 29.4)
  line L7 (32, 29.4) -> (34.4, 29.4)
  line L8 (32, 32.4) -> (32, 4.4)
  line L9 (30, 2.4) -> (32, 4.4)
  line L10 (30, 2.4) -> (30, 0)
  line L11 (43.26, 22.4) -> (36.26, 15.4)
  line L12 (36.26, 15.4) -> (36.26, 2.6355)
  line L13 (36.26, 2.6355) -> (33.6245, 0)
  arc A1 centre (38.26, 27.4) radius 5 clockwise from (38.26, 32.4) to (43.26, 27.4)
  circle C1 centre (38.76, 24.4) radius 1.7
  circle C2 centre (38.76, 24.4) radius 1.425
  concentric C1 C2
  dimension "d42" diameter C2 = 2.85 (= "ScrewThreadDiameter")
extrude "Extrude13" add sketch "Sketch9" profile of L2 L3 A1 L4 L5 L6 L7 L8 L9 L10 C2 L11 L12 L13 along a picked direction blind 3.2 (= "HingeLatchRibWidth") named "d87_1"
work_plane "WorkPlane8" AlongDistance -47.5 (= "HingeLatchOffset - InnerBoxWidth / 2 + ScrewLength / 2")
sketch "Sketch12" plane through (0, 0, -47.5) normal (0, 0, 1) x axis (1, 0, 0)
  line L1 (-34.4, 22.1317) -> (-42.2642, 29.9958)
  line L2 (-36.46, 32.4) -> (-36.26, 32.4)
  line L3 (-36.26, 29.4) -> (-36.26, 32.4)
  line L4 (-36.26, 29.4) -> (-34.4, 25)
  line L5 (-34.4, 3.4059) -> (-34.4, 25)
  line L6 (-43.26, 3.0735) -> (-43.26, 27.4)
  line L7 (-43.26, 32.4) -> (-43.26, 27.4)
  line L8 (-43.26, 3.0735) -> (-40.1865, 0)
  line L9 (-30, 0) -> (-40.1865, 0)
  line L10 (-34.4, 3.4059) -> (-30.9941, 0)
  line L11 (-36.26, 2.6355) -> (-33.6245, 0)
  line L12 (-43.26, 27.4) -> (-36.26, 20.4)
  line L13 (-36.26, 20.4) -> (-36.26, 2.6355)
  circle C1 centre (-39.86, 32.4) radius 3.4
  circle C2 centre (-39.86, 32.4) radius 1.7
extrude "Extrude19" add sketch "Sketch12" profile of L1 C1 C2 L2 L3 L4 L5 along a picked direction no distance stored
extrude "Extrude21" add sketch "Sketch12" profile of L1 C1 L5 L6 L7 L9 L10 L12 L13 L11 along a picked direction distance 1.6 (= "HingeLatchRibWidth / 2")
work_plane "WorkPlane9" AlongDistance 47.5 (= "InnerBoxWidth / 2 - HingeLatchOffset - ScrewLength / 2")
sketch "Sketch13" plane through (0, 0, 47.5) normal (0, 0, 1) x axis (1, 0, 0)
  line L1 (-34.4, 22.1317) -> (-42.2642, 29.9958)
  line L2 (-36.26, 29.4) -> (-34.4, 25)
  line L3 (-34.4, 3.4059) -> (-34.4, 25)
  line L4 (-36.26, 29.4) -> (-36.26, 32.4)
  line L5 (-36.46, 32.4) -> (-36.26, 32.4)
  line L6 (-43.26, 3.0735) -> (-43.26, 27.4)
  line L7 (-43.26, 32.4) -> (-43.26, 27.4)
  line L8 (-43.26, 3.0735) -> (-40.1865, 0)
  line L9 (-30, 0) -> (-40.1865, 0)
  line L10 (-34.4, 3.4059) -> (-30.9941, 0)
  line L11 (-36.26, 2.6355) -> (-33.6245, 0)
  line L12 (-43.26, 27.4) -> (-36.26, 20.4)
  line L13 (-36.26, 20.4) -> (-36.26, 2.6355)
  circle C1 centre (-39.86, 32.4) radius 3.4
  circle C2 centre (-39.86, 32.4) radius 1.7
extrude "Extrude20" add sketch "Sketch13" profile of L1 L2 L3 L4 C1 C2 L5 along a picked direction no distance stored
extrude "Extrude22" add sketch "Sketch13" profile of L1 L3 C1 L6 L7 L9 L10 L12 L13 L11 along a picked direction distance 1.6 (= "HingeLatchRibWidth / 2")
fillet "Fillet2" radius 1
fillet "Fillet3" radius 3
component_from_bodies "Body->Comp1"
joint "Assemble1" alignAngle 180 alignOffsetX 0 alignOffsetY 0 alignOffsetZ 0.125 (= "HingeWidthTolerance / 2") AngleMinimum -180 AngleMaximum 0
sketch "Sketch1" plane through (0, 0, 30.4) normal (0, 0, 1) x axis (-1, 0, 0)
extrude "Extrude1" new body of existing geometry blind 1.4 (= "SealHeight") bodies "Box - Seal"
ground "Ground1"
joint "Assemble2" alignAngle 180 alignOffsetX 0 alignOffsetY 0 alignOffsetZ 0.2 (= "LatchWidthTolerance / 2") AngleMinimum 0 AngleMaximum 185
mirror "Mirror2" mirrorStitchTolerance 0.1 bodies "Box - Latch (1)"
component_insert "Component Insert"
sketch "Sketch1" plane through (0, 0, 2.4) normal (0, 0, 1) x axis (-1, 0, 0)
  line L1 (80, -30) -> (-80, -30)
  line L2 (83, 27) -> (83, -27)
  line L3 (-80, 30) -> (80, 30)
  line L4 (-83, -27) -> (-83, 27)
  line L5 (85, 27) -> (85, -27)
  line L6 (-80, 32) -> (80, 32)
  line L7 (-85, -27) -> (-85, 27)
  line L8 (80, -32) -> (-80, -32)
  line L9 (30, 25) -> (-30, 25)
  line L10 (30, -25) -> (30, 25)
  line L11 (-30, -25) -> (30, -25)
  line L12 (-30, 25) -> (-30, -25)
  line L13 (30, -25) -> (-30, 25)
  line L14 (-30, -25) -> (30, 25)
  arc A1 centre (-80, -27) radius 3 clockwise from (-80, -30) to (-83, -27)
  arc A2 centre (80, -27) radius 3 clockwise from (83, -27) to (80, -30)
  arc A3 centre (80, 27) radius 3 clockwise from (80, 30) to (83, 27)
  arc A4 centre (-80, 27) radius 3 clockwise from (-83, 27) to (-80, 30)
  arc A5 centre (80, 27) radius 5 clockwise from (80, 32) to (85, 27)
  arc A6 centre (-80, 27) radius 5 clockwise from (-85, 27) to (-80, 32)
  arc A7 centre (-80, -27) radius 5 clockwise from (-80, -32) to (-85, -27)
  arc A8 centre (80, -27) radius 5 clockwise from (85, -27) to (80, -32)
  point P30 (0, 0)
  point P1 (0, 0)
  point P28 (30, -25)
  point P29 (-30, -25)
  point P27 (30, 25)
  horizontal L9
  perpendicular L9 L10
  parallel L9 L11
  parallel L10 L12
  coincident L13 P30
  coincident L14 P30
  coincident P1 P30
  dimension "d150" = 2 (= "InnerChamferSize")
  dimension "d187" distance P28 P29 = 60
  dimension "d188" distance P27 P28 = 50
extrude "Extrude5" new body sketch "Sketch1" profile of L9 L10 L11 L12 blind -25 from offset 30
extrude "Extrude1" new body sketch "Sketch1" profile of A1 L1 A2 L2 A3 L3 A4 L4 A8 L7 L8 A6 L5 A5 A7 L6 along normal blind 60 (= "InnerBoxBottomHeight + InnerBoxLidHeight")
combine "Combine1"
work_plane "WorkPlane1"
split "Split1"
move "Move1"
align "Align1"
offset_faces "OffsetFaces1" distance -0.5
offset_faces "OffsetFaces2" distance -0.5
position "Position1"
chamfer "Chamfer1" distance 1
chamfer "Chamfer2" distance 0.6
fillet "Fillet1" radius 5
fillet "Fillet2" radius 2
combine "Combine2"
combine "Combine3"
